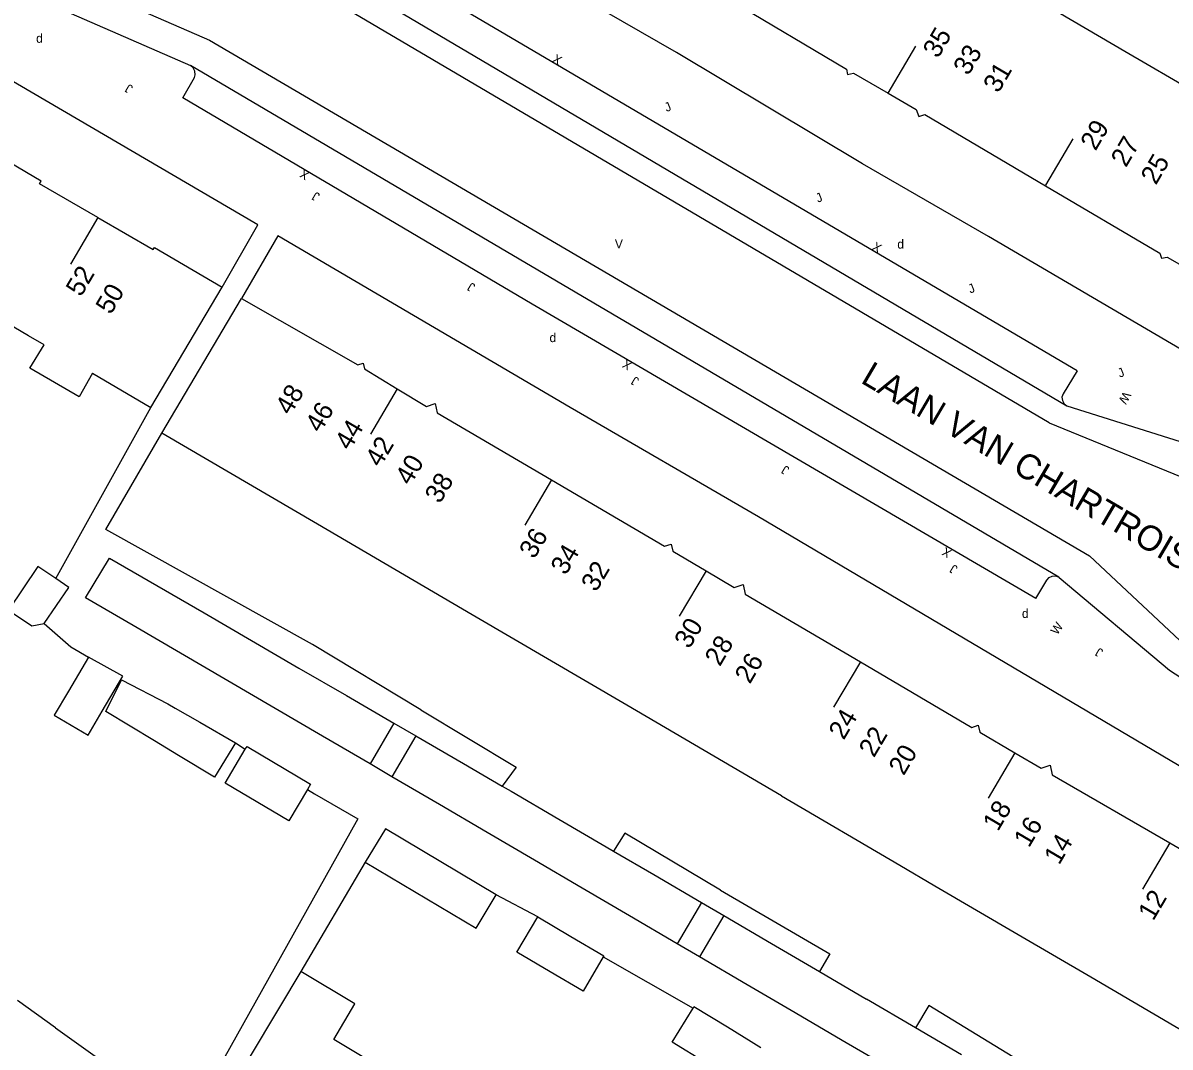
# Model space of a CAD drawing. Extents: x 134999 to 136502, y 457398 to 459002.
# Drawn here: x 135611.3 to 135675.1, y 457507.4 to 457564.4 of the extents above; entities that cross this region are included whole.
import ezdxf

# ---------------------------------------------------------------- set-up
doc = ezdxf.new("R2010")
doc.units = 0
for name, color, linetype in [('RI_DGTB_15', 7, 'Continuous'), ('RI_DGTB_29', 7, 'Continuous'), ('RI_DGTB_30', 7, 'Continuous'), ('RI_DGTB_31', 7, 'Continuous'), ('RI_DGTB_35', 7, 'Continuous'), ('RI_DGTB_36', 7, 'Continuous'), ('RI_DGTB_37', 7, 'Continuous'), ('RI_DGTB_4', 7, 'Continuous'), ('RI_DGTB_5', 7, 'Continuous'), ('RI_DGTB_53', 7, 'Continuous'), ('RI_DGTB_54', 7, 'Continuous'), ('RI_DGTB_6', 7, 'Continuous'), ('RI_DGTB_7', 7, 'Continuous')]:
    doc.layers.add(name, color=color, linetype=linetype)

msp = doc.modelspace()

# ---------------------------------------------------------------- linework, layer by layer
at = {"layer": 'RI_DGTB_15'}
for p, q in [((135659.387, 457560.437), (135660.92, 457563.052)), ((135668.159, 457555.327), (135669.677, 457557.915)), ((135615.466, 457553.525), (135613.947, 457550.939)), ((135632.105, 457544.013), (135630.613, 457541.482)), ((135640.679, 457538.94), (135639.194, 457536.422)), ((135649.265, 457533.89), (135647.775, 457531.362)), ((135657.845, 457528.827), (135656.356, 457526.302)), ((135666.43, 457523.773), (135664.937, 457521.242)), ((135675.042, 457518.766), (135673.518, 457516.182))]:
    msp.add_line(p, q, dxfattribs=at)
at = {"layer": 'RI_DGTB_4'}
for p, q in [((135618.407, 457542.968), (135622.373, 457549.653)), ((135619.026, 457541.545), (135623.455, 457549.028)), ((135611.61, 457546.961), (135610.39, 457547.677)), ((135612.483, 457546.448), (135611.61, 457546.961)), ((135615.164, 457544.873), (135618.407, 457542.968))]:
    msp.add_line(p, q, dxfattribs=at)
for points in [[(135650.642, 457565.596), (135657.08, 457561.777), (135657.129, 457561.49), (135657.469, 457561.553), (135659.387, 457560.437)], [(135659.387, 457560.437), (135660.946, 457559.53), (135661.086, 457559.14), (135661.418, 457559.254), (135668.138, 457555.291)], [(135615.466, 457553.525), (135612.224, 457555.402), (135612.313, 457555.561), (135608.852, 457557.594)], [(135668.138, 457555.291), (135674.483, 457551.55), (135674.572, 457551.275), (135674.891, 457551.32), (135676.906, 457550.174)], [(135615.466, 457553.525), (135618.538, 457551.747), (135618.614, 457551.874), (135622.373, 457549.653)], [(135623.455, 457549.028), (135629.907, 457545.341), (135630.219, 457545.432), (135630.291, 457545.111), (135632.105, 457544.013)], [(135632.105, 457544.013), (135633.724, 457543.033), (135634.216, 457543.195), (135634.327, 457542.666), (135640.679, 457538.94)], [(135640.679, 457538.94), (135646.953, 457535.261), (135647.329, 457535.367), (135647.414, 457534.989), (135649.265, 457533.89)], [(135649.265, 457533.89), (135650.826, 457532.964), (135651.327, 457533.128), (135651.438, 457532.599), (135657.845, 457528.827)], [(135657.845, 457528.827), (135664.041, 457525.179), (135664.393, 457525.307), (135664.48, 457524.922), (135666.43, 457523.773)], [(135666.43, 457523.773), (135667.885, 457522.916), (135668.388, 457523.082), (135668.499, 457522.553), (135675.036, 457518.756)], [(135675.036, 457518.756), (135681.227, 457515.159), (135681.603, 457515.265), (135681.688, 457514.887), (135683.638, 457513.73)], [(135625.57, 457509.629), (135623.827, 457506.712), (135623.687, 457506.77), (135623.509, 457506.444), (135623.594, 457506.391)]]:
    msp.add_lwpolyline(points, dxfattribs=at)
at = {"layer": 'RI_DGTB_5'}
for p, q in [((135663.775, 457567.922), (135672.535, 457562.788)), ((135672.535, 457562.788), (135681.295, 457557.654)), ((135627.666, 457536.483), (135619.026, 457541.545)), ((135636.261, 457531.448), (135627.666, 457536.483)), ((135644.858, 457526.412), (135636.261, 457531.448)), ((135653.452, 457521.377), (135644.858, 457526.412)), ((135660.036, 457517.52), (135661.983, 457516.38)), ((135661.983, 457516.38), (135666.605, 457513.672)), ((135626.751, 457511.604), (135625.57, 457509.629)), ((135670.643, 457511.307), (135679.238, 457506.274)), ((135613.115, 457508.475), (135611.006, 457509.998))]:
    msp.add_line(p, q, dxfattribs=at)
for points in [[(135615.164, 457544.873), (135614.432, 457543.553), (135611.683, 457545.161), (135612.483, 457546.448)], [(135653.452, 457521.377), (135660.036, 457517.52)], [(135666.605, 457513.672), (135670.643, 457511.307)], [(135631.641, 457506.003), (135628.576, 457507.835), (135629.756, 457509.809), (135626.751, 457511.604)], [(135613.115, 457508.475), (135615.455, 457506.808)]]:
    msp.add_lwpolyline(points, dxfattribs=at)
at = {"layer": 'RI_DGTB_53'}
for p, q in [((135620.853, 457571.714), (135669.314, 457543.069)), ((135668.864, 457533.542), (135620.608, 457561.99)), ((135668.334, 457542.11), (135679.783, 457537.421)), ((135670.576, 457534.713), (135676.501, 457529.167))]:
    msp.add_line(p, q, dxfattribs=at)
for points in [[(135668.334, 457542.11), (135619.307, 457571.027), (135608.157, 457579.696), (135608.927, 457580.734)], [(135608.773, 457567.152), (135609.43, 457568.723), (135621.671, 457563.388), (135670.576, 457534.713)], [(135608.773, 457567.152), (135620.608, 457561.99)], [(135620.198, 457560.188), (135620.829, 457561.309), (135620.872, 457561.466), (135620.855, 457561.671), (135620.763, 457561.855), (135620.608, 457561.99)], [(135669.887, 457545.016), (135669.105, 457543.733), (135669.048, 457543.545), (135669.071, 457543.35), (135669.169, 457543.18), (135669.314, 457543.069)], [(135669.314, 457543.069), (135677.97, 457540.33), (135678.19, 457540.16), (135690.33, 457533.07), (135699.876, 457527.463)], [(135667.586, 457532.346), (135668.208, 457533.363), (135668.33, 457533.511), (135668.502, 457533.598), (135668.693, 457533.607), (135668.864, 457533.542)], [(135668.864, 457533.542), (135668.873, 457533.539), (135668.897, 457533.523)], [(135668.897, 457533.523), (135675.024, 457528.357), (135680.57, 457524.79), (135694.604, 457516.486)]]:
    msp.add_lwpolyline(points, dxfattribs=at)
at = {"layer": 'RI_DGTB_54'}
for p, q in [((135613.123, 457533.459), (135618.407, 457542.968)), ((135630.33, 457517.686), (135626.751, 457511.604)), ((135639.918, 457514.651), (135637.6, 457515.879)), ((135643.558, 457512.419), (135648.552, 457509.578))]:
    msp.add_line(p, q, dxfattribs=at)
for points in [[(135703.231, 457534.763), (135701.167, 457531.303), (135693.165, 457536.051), (135682.674, 457542.151), (135675.664, 457546.201), (135664.972, 457552.474), (135657.962, 457556.524), (135647.625, 457562.705), (135640.615, 457566.755), (135630.338, 457572.795), (135623.328, 457576.845), (135612.848, 457583.095), (135604.749, 457587.784), (135606.791, 457591.268)], [(135669.887, 457545.016), (135633.769, 457566.278), (135622.27, 457573.017)], [(135622.373, 457549.653), (135624.352, 457553.133), (135602.631, 457565.856), (135600.537, 457562.477)], [(135667.586, 457532.346), (135639.606, 457548.722), (135620.198, 457560.188)], [(135691.135, 457509.376), (135693.104, 457512.793), (135686.451, 457516.786), (135684.486, 457517.816), (135677.786, 457521.722), (135652.177, 457536.888), (135641.712, 457542.966), (135625.464, 457552.52), (135623.455, 457549.028)], [(135633.42, 457526.161), (135627.387, 457529.79), (135615.91, 457536.18), (135619.026, 457541.545)], [(135612.49, 457530.955), (135613.962, 457529.656), (135614.946, 457529.096)], [(135627.117, 457521.737), (135627.514, 457521.481), (135629.911, 457520.101), (135622.426, 457506.692), (135619.035, 457500.507), (135616.559, 457501.995), (135612.806, 457496.985), (135608.729, 457499.548), (135604.059, 457502.67), (135591.362, 457511.707), (135573.562, 457524.581), (135574.705, 457526.179)], [(135633.42, 457526.161), (135638.72, 457522.97), (135637.938, 457521.921)], [(135623.109, 457524.323), (135623.661, 457523.967)], [(135650.064, 457516.131), (135644.759, 457519.297), (135644.131, 457518.308)], [(135650.064, 457516.131), (135656.144, 457512.591), (135655.568, 457511.604)], [(135672.882, 457501.453), (135673.561, 457502.438), (135661.641, 457509.721), (135660.911, 457508.472)]]:
    msp.add_lwpolyline(points, dxfattribs=at)
at = {"layer": 'RI_DGTB_6'}
for p, q in [((135631.92, 457525.416), (135630.594, 457523.151)), ((135633.139, 457524.708), (135631.812, 457522.44)), ((135649.006, 457515.45), (135647.661, 457513.153)), ((135650.258, 457514.717), (135648.912, 457512.42)), ((135655.568, 457511.604), (135658.187, 457510.069)), ((135660.911, 457508.472), (135658.187, 457510.069))]:
    msp.add_line(p, q, dxfattribs=at)
for points in [[(135613.123, 457533.459), (135612.138, 457534.127), (135610.501, 457531.701), (135611.799, 457530.821), (135612.49, 457530.955)], [(135617.434, 457530.844), (135614.778, 457532.396), (135616.107, 457534.6), (135618.737, 457533.073)], [(135612.49, 457530.955), (135613.848, 457532.967), (135613.123, 457533.459)], [(135618.737, 457533.073), (135621.368, 457531.545)], [(135621.368, 457531.545), (135623.998, 457530.017)], [(135620.06, 457529.309), (135617.434, 457530.844)], [(135623.998, 457530.017), (135626.638, 457528.484)], [(135614.946, 457529.096), (135613.831, 457527.196)], [(135615.712, 457526.087), (135616.856, 457528.033), (135614.946, 457529.096)], [(135622.686, 457527.774), (135620.06, 457529.309)], [(135626.638, 457528.484), (135629.279, 457526.95)], [(135618.606, 457524.434), (135615.901, 457526.071), (135616.781, 457527.826), (135619.353, 457526.498), (135619.765, 457526.259)], [(135625.323, 457526.232), (135622.686, 457527.774)], [(135613.831, 457527.196), (135613.048, 457525.867), (135614.929, 457524.758), (135615.712, 457526.087)], [(135629.279, 457526.95), (135631.92, 457525.416)], [(135619.765, 457526.259), (135621.126, 457525.471)], [(135627.959, 457524.691), (135625.323, 457526.232)], [(135621.126, 457525.471), (135623.109, 457524.323)], [(135630.594, 457523.151), (135627.959, 457524.691)], [(135633.139, 457524.708), (135635.787, 457523.17)], [(135619.951, 457523.621), (135618.606, 457524.434)], [(135623.109, 457524.323), (135621.952, 457522.411), (135619.951, 457523.621)], [(135627.117, 457521.737), (135626.075, 457519.985), (135622.543, 457522.087), (135623.661, 457523.967)], [(135623.661, 457523.967), (135623.758, 457524.13)], [(135623.758, 457524.13), (135627.29, 457522.028), (135627.117, 457521.737)], [(135635.787, 457523.17), (135637.938, 457521.921)], [(135634.455, 457520.891), (135631.812, 457522.44)], [(135637.938, 457521.921), (135638.435, 457521.631)], [(135638.435, 457521.631), (135641.08, 457520.088)], [(135637.097, 457519.343), (135634.455, 457520.891)], [(135641.08, 457520.088), (135643.724, 457518.546)], [(135637.6, 457515.879), (135631.451, 457519.542), (135630.33, 457517.686)], [(135639.736, 457517.797), (135637.097, 457519.343)], [(135643.724, 457518.546), (135644.131, 457518.308)], [(135644.131, 457518.308), (135646.365, 457516.998)], [(135630.33, 457517.686), (135636.494, 457514.013), (135637.6, 457515.879)], [(135642.378, 457516.249), (135639.736, 457517.797)], [(135646.365, 457516.998), (135649.006, 457515.45)], [(135645.019, 457514.701), (135642.378, 457516.249)], [(135640.595, 457511.597), (135638.758, 457512.681), (135639.918, 457514.651)], [(135639.918, 457514.651), (135641.757, 457513.566)], [(135647.661, 457513.153), (135645.019, 457514.701)], [(135650.258, 457514.717), (135652.901, 457513.168)], [(135641.757, 457513.566), (135643.595, 457512.482), (135643.558, 457512.419)], [(135652.901, 457513.168), (135655.568, 457511.604)], [(135643.558, 457512.419), (135642.435, 457510.512), (135640.595, 457511.597)], [(135651.555, 457510.871), (135648.912, 457512.42)], [(135654.222, 457509.307), (135651.555, 457510.871)], [(135649.251, 457506.539), (135647.387, 457507.68), (135648.552, 457509.578)], [(135650.456, 457508.512), (135648.596, 457509.649), (135648.552, 457509.578)], [(135656.84, 457507.773), (135654.222, 457509.307)], [(135652.317, 457507.374), (135650.456, 457508.512)], [(135663.472, 457506.97), (135660.911, 457508.472)], [(135659.565, 457506.176), (135656.84, 457507.773)]]:
    msp.add_lwpolyline(points, dxfattribs=at)
at = {"layer": 'RI_DGTB_7'}
for p, q in [((135631.92, 457525.416), (135633.139, 457524.708)), ((135631.812, 457522.44), (135630.594, 457523.151)), ((135649.006, 457515.45), (135650.258, 457514.717)), ((135648.912, 457512.42), (135647.661, 457513.153))]:
    msp.add_line(p, q, dxfattribs=at)

# ---------------------------------------------------------------- texts
at = {"layer": 'RI_DGTB_29'}
for p in [(135612.037, 457563.246), (135659.896, 457551.802), (135640.567, 457546.605), (135666.821, 457531.27)]:
    msp.add_text('d', height=0.5, dxfattribs=at).set_placement(p)
at = {"layer": 'RI_DGTB_30'}
for s, height, rotation, p in [('X', 0.499, 329.59238, (135640.68, 457562.216)), ('X', 0.499, 149.58963, (135627.268, 457556.018)), ('X', 0.499, 329.59238, (135658.448, 457551.773)), ('X', 0.499, 149.58963, (135645.196, 457545.439)), ('W', 0.5, 240.94566, (135672.477, 457543.901)), ('X', 0.499, 149.58963, (135662.96, 457535.006)), ('W', 0.5, 55.30787, (135668.784, 457530.287))]:
    msp.add_text(s, height=height, rotation=rotation, dxfattribs=at).set_placement(p)
msp.add_text('V', height=0.5, dxfattribs=at).set_placement((135644.2, 457551.812))
at = {"layer": 'RI_DGTB_31'}
for rotation, p in [(149.67012, (135617.458, 457560.82)), (21.89644, (135647.076, 457559.394)), (149.67012, (135627.847, 457554.826)), (21.89644, (135655.482, 457554.348)), (149.67012, (135636.482, 457549.785)), (21.89644, (135663.952, 457549.3)), (21.89644, (135672.263, 457544.618)), (149.67012, (135645.587, 457544.563)), (149.67012, (135653.936, 457539.615)), (149.67012, (135663.29, 457534.107)), (149.67012, (135671.378, 457529.476))]:
    msp.add_text('J', height=0.5, rotation=rotation, dxfattribs=at).set_placement(p)
at = {"layer": 'RI_DGTB_35'}
for s, rotation, p in [('50', 59.5729, (135616.188, 457548.088)), ('48', 59.4644, (135626.166, 457542.49))]:
    msp.add_text(s, height=1.054, rotation=rotation, dxfattribs=at).set_placement(p)
at = {"layer": 'RI_DGTB_36'}
for s, rotation, p in [('35', 59.6085, (135662.157, 457562.334)), ('33', 59.6143, (135663.848, 457561.38)), ('31', 59.6085, (135665.513, 457560.405)), ('29', 59.6085, (135670.913, 457557.195)), ('27', 59.6143, (135672.606, 457556.276)), ('25', 59.6085, (135674.269, 457555.299)), ('52', 59.5729, (135614.532, 457549.082)), ('46', 59.4644, (135627.833, 457541.512)), ('44', 59.4644, (135629.473, 457540.532)), ('42', 59.4644, (135631.164, 457539.598)), ('40', 59.4644, (135632.832, 457538.586)), ('38', 59.4644, (135634.477, 457537.576)), ('36', 59.4644, (135639.723, 457534.502)), ('34', 59.4644, (135641.471, 457533.599)), ('32', 59.4644, (135643.163, 457532.666)), ('30', 59.4644, (135648.343, 457529.506)), ('28', 59.4644, (135650.035, 457528.53)), ('26', 59.4644, (135651.702, 457527.555)), ('24', 59.4644, (135656.919, 457524.439)), ('22', 59.4644, (135658.599, 457523.462)), ('20', 59.4644, (135660.253, 457522.462)), ('18', 59.4644, (135665.488, 457519.358)), ('16', 59.4644, (135667.212, 457518.451)), ('14', 59.4644, (135668.89, 457517.495)), ('12', 59.4644, (135674.118, 457514.383))]:
    msp.add_text(s, height=1.054, rotation=rotation, dxfattribs=at).set_placement(p)
at = {"layer": 'RI_DGTB_37'}
msp.add_text('LAAN VAN CHARTROISE', height=1.4, rotation=329.57093, dxfattribs=at).set_placement((135657.802, 457544.377))

doc.saveas('drawing.dxf')
